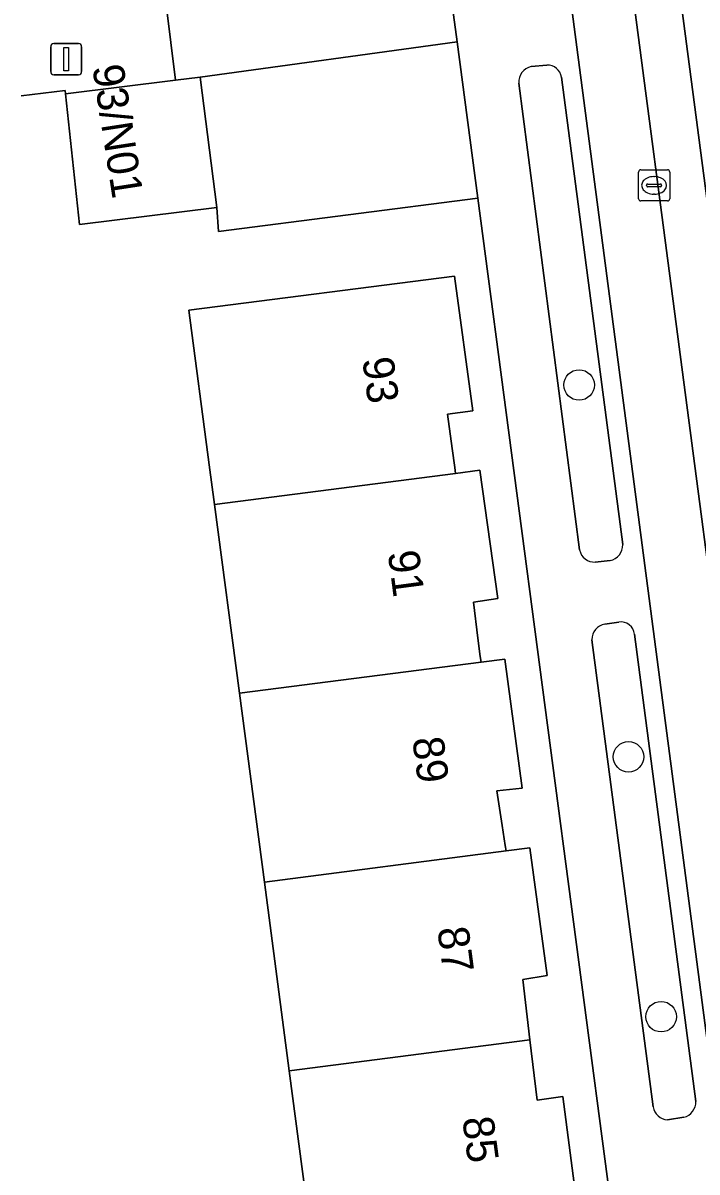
# Model space of a CAD drawing. Extents: x 160554 to 161248, y 385329 to 386506.
# Drawn here: x 161050.48 to 161072.1, y 386001.43 to 386038.26 of the extents above; entities that cross this region are included whole.
import ezdxf

# ---------------------------------------------------------------- set-up
doc = ezdxf.new("R2010")
doc.units = 0
for name, color, linetype in [('IMGEO_Boom', 7, 'Continuous'), ('IMGEO_Erf', 7, 'Continuous'), ('IMGEO_Groenvoorziening', 7, 'Continuous'), ('IMGEO_Kolk', 7, 'Continuous'), ('IMGEO_Lichtmast', 7, 'Continuous'), ('IMGEO_Pand', 7, 'Continuous'), ('IMGEO_Pand_nummerreeks', 7, 'Continuous'), ('IMGEO_Parkeervlak_open', 7, 'Continuous'), ('IMGEO_Rijbaan_lokaal_gesloten', 7, 'Continuous'), ('IMGEO_Rijbaan_lokaal_open', 7, 'Continuous'), ('IMGEO_Voetpad_open', 7, 'Continuous')]:
    doc.layers.add(name, color=color, linetype=linetype)

msp = doc.modelspace()

# ---------------------------------------------------------------- linework, layer by layer
at = {"layer": 'IMGEO_Boom'}
for centre in [(161068.314, 386026.655), (161069.899, 386014.74), (161070.944, 386006.411)]:
    msp.add_circle(centre, 0.489, dxfattribs=at)
at = {"layer": 'IMGEO_Erf'}
for points in [[(161069.382, 386000), (161065.063, 386032.642), (161056.745, 386031.578), (161056.695, 386032.348), (161052.296, 386031.803), (161051.839, 386035.985), (161051.828, 386036.088), (161050.417, 386035.918)], [(161059.638, 386000), (161059.02, 386004.678), (161058.22, 386010.727), (161057.421, 386016.777), (161056.622, 386022.826), (161056.454, 386024.095), (161055.798, 386029.051), (161064.319, 386030.143), (161064.901, 386025.824), (161064.099, 386025.724), (161064.244, 386024.624), (161064.325, 386024.008), (161064.35, 386023.82), (161065.131, 386023.921), (161065.707, 386019.81), (161064.925, 386019.691), (161065.072, 386018.539), (161065.146, 386017.959), (161065.17, 386017.773), (161065.937, 386017.872), (161066.49, 386013.738), (161065.68, 386013.644), (161065.848, 386012.537), (161065.946, 386011.897), (161065.972, 386011.724), (161066.735, 386011.822), (161067.285, 386007.729), (161066.511, 386007.598), (161066.738, 386005.671), (161066.966, 386003.741), (161067.794, 386003.854), (161068.292, 386000)]]:
    msp.add_lwpolyline(points, dxfattribs=at)
at = {"layer": 'IMGEO_Groenvoorziening'}
for points in [[(161067.284, 386036.908), (161066.777, 386036.857)], [(161069.717, 386021.54), (161067.748, 386036.516)], [(161066.379, 386036.33), (161068.33, 386021.369)], [(161068.834, 386020.98), (161069.307, 386021.028)], [(161069.591, 386019.058), (161069.138, 386018.992)], [(161068.722, 386018.493), (161070.691, 386003.517)], [(161072.061, 386003.692), (161070.092, 386018.668)], [(161071.144, 386003.109), (161071.672, 386003.188)]]:
    msp.add_lwpolyline(points, dxfattribs=at)
for centre, radius, start, end in [((161066.871, 386036.373), 0.493, 100.9362, 184.9423), ((161067.296, 386036.452), 0.456, 8.0548, 91.5611), ((161068.804, 386021.463), 0.483, 191.1541, 273.5222), ((161069.208, 386021.528), 0.509, 281.2229, 1.4029), ((161069.656, 386018.625), 0.438, 5.602, 98.6005), ((161069.237, 386018.487), 0.515, 101.0402, 179.326), ((161071.539, 386003.693), 0.522, 284.7727, 359.9036), ((161071.175, 386003.599), 0.491, 189.5958, 266.3879)]:
    msp.add_arc(centre, radius, start, end, dxfattribs=at)
at = {"layer": 'IMGEO_Kolk'}
for p, q in [((161070.219, 386032.626), (161070.219, 386033.478)), ((161070.294, 386033.552), (161071.146, 386033.552)), ((161071.22, 386033.478), (161071.22, 386032.626)), ((161070.478, 386033.046), (161070.478, 386033.058)), ((161070.521, 386033.095), (161070.919, 386033.095)), ((161070.707, 386033.332), (161070.732, 386033.332)), ((161070.962, 386033.058), (161070.962, 386033.046)), ((161070.916, 386033.009), (161070.518, 386033.009)), ((161070.73, 386032.772), (161070.705, 386032.772)), ((161071.146, 386032.552), (161070.294, 386032.552))]:
    msp.add_line(p, q, dxfattribs=at)
for points in [[(161070.219, 386032.626), (161070.219, 386033.478)], [(161070.294, 386033.552), (161071.146, 386033.552)], [(161071.22, 386033.478), (161071.22, 386032.626)], [(161071.146, 386032.552), (161070.294, 386032.552)]]:
    msp.add_lwpolyline(points, dxfattribs=at)
for centre, radius, start, end in [((161070.296, 386033.476), 0.0765, 91.552, 178.448), ((161070.296, 386033.476), 0.0765, 91.552, 178.448), ((161071.144, 386033.476), 0.0765, 1.552, 88.448), ((161071.144, 386033.476), 0.0765, 1.552, 88.448), ((161070.518, 386033.055), 0.0403, 85.8775, 175.7526), ((161070.515, 386033.045), 0.0366, 178.938, 274.7102), ((161070.919, 386033.052), 0.043, 264.8664, 352.4533), ((161070.923, 386033.057), 0.0386, 1.7309, 96.639), ((161070.296, 386032.628), 0.0765, 181.552, 268.448), ((161070.296, 386032.628), 0.0765, 181.552, 268.448), ((161071.144, 386032.628), 0.0765, 271.552, 358.448), ((161071.144, 386032.628), 0.0765, 271.552, 358.448)]:
    msp.add_arc(centre, radius, start, end, dxfattribs=at)
for centre, major_axis, ratio, start_param, end_param in [((161070.706, 386033.052), (-0.387, 0.002), 0.722429, 4.712389, 7.853982), ((161070.731, 386033.052), (-0.39, 0.002), 0.717154, 1.570796, 4.712389)]:
    msp.add_ellipse(centre, major_axis=major_axis, ratio=ratio, start_param=start_param, end_param=end_param, dxfattribs=at)
at = {"layer": 'IMGEO_Lichtmast'}
for p, q in [((161051.37, 386036.697), (161051.37, 386037.497)), ((161051.37, 386037.497), (161051.37, 386036.697)), ((161051.47, 386037.597), (161052.26, 386037.597)), ((161052.26, 386037.597), (161051.47, 386037.597)), ((161052.36, 386037.497), (161052.36, 386036.697)), ((161052.36, 386036.697), (161052.36, 386037.497)), ((161052.26, 386036.597), (161051.47, 386036.597)), ((161051.47, 386036.597), (161052.26, 386036.597))]:
    msp.add_line(p, q, dxfattribs=at)
msp.add_lwpolyline([(161051.79, 386037.472), (161051.94, 386037.472), (161051.94, 386036.722), (161051.79, 386036.722), (161051.79, 386037.472)], dxfattribs=at)
for centre, start, end in [((161051.47, 386037.497), 90, 180), ((161051.47, 386037.497), 90, 180), ((161052.26, 386037.497), 0, 90), ((161052.26, 386037.497), 360, 90), ((161051.47, 386036.697), 180, 270), ((161051.47, 386036.697), 180, 270), ((161052.26, 386036.697), 270, 0), ((161052.26, 386036.697), 270, 0)]:
    msp.add_arc(centre, 0.1, start, end, dxfattribs=at)
at = {"layer": 'IMGEO_Pand'}
for points in [[(161051.839, 386035.985), (161052.296, 386031.803), (161056.695, 386032.348), (161056.161, 386036.518), (161055.368, 386036.42)], [(161056.622, 386022.826), (161064.35, 386023.82), (161064.325, 386024.008), (161064.244, 386024.624), (161064.099, 386025.724), (161064.901, 386025.824), (161064.319, 386030.143), (161055.798, 386029.051), (161056.454, 386024.095)], [(161064.35, 386023.82), (161056.622, 386022.826), (161057.421, 386016.777), (161065.17, 386017.773), (161065.146, 386017.959), (161065.072, 386018.539), (161064.925, 386019.691), (161065.707, 386019.81), (161065.131, 386023.921)], [(161065.17, 386017.773), (161057.421, 386016.777), (161058.22, 386010.727), (161065.972, 386011.724), (161065.946, 386011.897), (161065.848, 386012.537), (161065.68, 386013.644), (161066.49, 386013.738), (161065.937, 386017.872)], [(161066.735, 386011.822), (161065.972, 386011.724), (161058.22, 386010.727), (161059.02, 386004.678), (161066.738, 386005.671), (161066.511, 386007.598), (161067.285, 386007.729)], [(161067.794, 386003.854), (161066.966, 386003.741), (161066.738, 386005.671), (161059.02, 386004.678), (161059.638, 386000), (161059.819, 385998.629), (161067.517, 385999.619), (161068.328, 385999.723), (161068.292, 386000)]]:
    msp.add_lwpolyline(points, close=True, dxfattribs=at)
at = {"layer": 'IMGEO_Parkeervlak_open'}
for points in [[(161081.581, 385937.098), (161083.425, 385937.348), (161074.169, 386007.952), (161074.015, 386008.997), (161073.237, 386014.893), (161073.09, 386015.931), (161068.384, 386051.777)], [(161066.54, 386050.434), (161077.499, 385966.964), (161078.278, 385961.032), (161081.396, 385937.282)]]:
    msp.add_lwpolyline(points, dxfattribs=at)
msp.add_lwpolyline([(161063.757, 386042.459), (161054.772, 386041.258), (161055.368, 386036.42), (161056.161, 386036.518), (161064.4, 386037.651)], close=True, dxfattribs=at)
at = {"layer": 'IMGEO_Rijbaan_lokaal_gesloten'}
msp.add_lwpolyline([(161065.335, 386075.084), (161065.354, 386074.934), (161066.618, 386065.254), (161066.623, 386065.212), (161066.918, 386062.96), (161067.093, 386061.671), (161067.992, 386054.799), (161068.384, 386051.777), (161073.09, 386015.931), (161074.577, 386016.14), (161066.82, 386075.134)], dxfattribs=at)
at = {"layer": 'IMGEO_Rijbaan_lokaal_open'}
for points in [[(161066.82, 386075.134), (161074.577, 386016.14), (161077.097, 386016.484), (161069.383, 386075.101)], [(161050.417, 386035.918), (161051.828, 386036.088), (161051.839, 386035.985), (161055.368, 386036.42), (161054.772, 386041.258), (161063.757, 386042.459), (161061.741, 386057.757), (161051.352, 386043.836), (161036.421, 386023.828)]]:
    msp.add_lwpolyline(points, dxfattribs=at)
at = {"layer": 'IMGEO_Voetpad_open'}
for points in [[(161059.284, 386076.675), (161061.087, 386062.538), (161061.384, 386060.454), (161061.741, 386057.757), (161063.757, 386042.459), (161064.4, 386037.651), (161065.063, 386032.642), (161069.382, 386000), (161073.924, 385966.182), (161074.387, 385962.734), (161074.404, 385962.606), (161074.645, 385960.809), (161077.722, 385937.898)], [(161081.396, 385937.282), (161078.278, 385961.032), (161077.105, 385960.883), (161076.309, 385966.835), (161077.499, 385966.964), (161066.54, 386050.434)], [(161066.777, 386036.857), (161067.284, 386036.908)], [(161067.748, 386036.516), (161069.717, 386021.54)], [(161068.33, 386021.369), (161066.379, 386036.33)], [(161069.307, 386021.028), (161068.834, 386020.98)], [(161069.138, 386018.992), (161069.591, 386019.058)], [(161070.691, 386003.517), (161068.722, 386018.493)], [(161070.092, 386018.668), (161072.061, 386003.692)], [(161071.672, 386003.188), (161071.144, 386003.109)]]:
    msp.add_lwpolyline(points, dxfattribs=at)
msp.add_lwpolyline([(161065.063, 386032.642), (161064.4, 386037.651), (161056.161, 386036.518), (161056.695, 386032.348), (161056.745, 386031.578)], close=True, dxfattribs=at)
for centre, radius, start, end in [((161066.871, 386036.373), 0.493, 100.9362, 184.9423), ((161067.296, 386036.452), 0.456, 8.0548, 91.5611), ((161068.804, 386021.463), 0.483, 191.1541, 273.5222), ((161069.208, 386021.528), 0.509, 281.2229, 1.4029), ((161069.656, 386018.625), 0.438, 5.602, 98.6005), ((161069.237, 386018.487), 0.515, 101.0402, 179.326), ((161071.539, 386003.693), 0.522, 284.7727, 359.9036), ((161071.175, 386003.599), 0.491, 189.5958, 266.3879)]:
    msp.add_arc(centre, radius, start, end, dxfattribs=at)

# ---------------------------------------------------------------- texts
at = {"layer": 'IMGEO_Pand_nummerreeks'}
for s, rotation, p in [('93/N01', 278.7462, (161052.701, 386036.854)), ('93', 277.5055, (161061.359, 386027.491)), ('91', 277.5055, (161062.175, 386021.295)), ('89', 277.5055, (161062.962, 386015.323)), ('87', 277.5055, (161063.764, 386009.239)), ('85', 277.5055, (161064.565, 386003.155))]:
    msp.add_text(s, height=1, rotation=rotation, dxfattribs=at).set_placement(p)

doc.saveas('drawing.dxf')
